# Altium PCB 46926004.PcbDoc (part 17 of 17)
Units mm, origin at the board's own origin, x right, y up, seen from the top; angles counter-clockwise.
Board outline 250 x 200 mm, 6 copper layers (Top Layer, INT1_GND, INT2_SIG, INT3_SIG, INT4_GND, Bottom Layer), stack 1.71 mm thick; 1450 components, 1293 nets, 5656 pads, 2307 vias.
Unrouted connection lines stored in the file: 2.
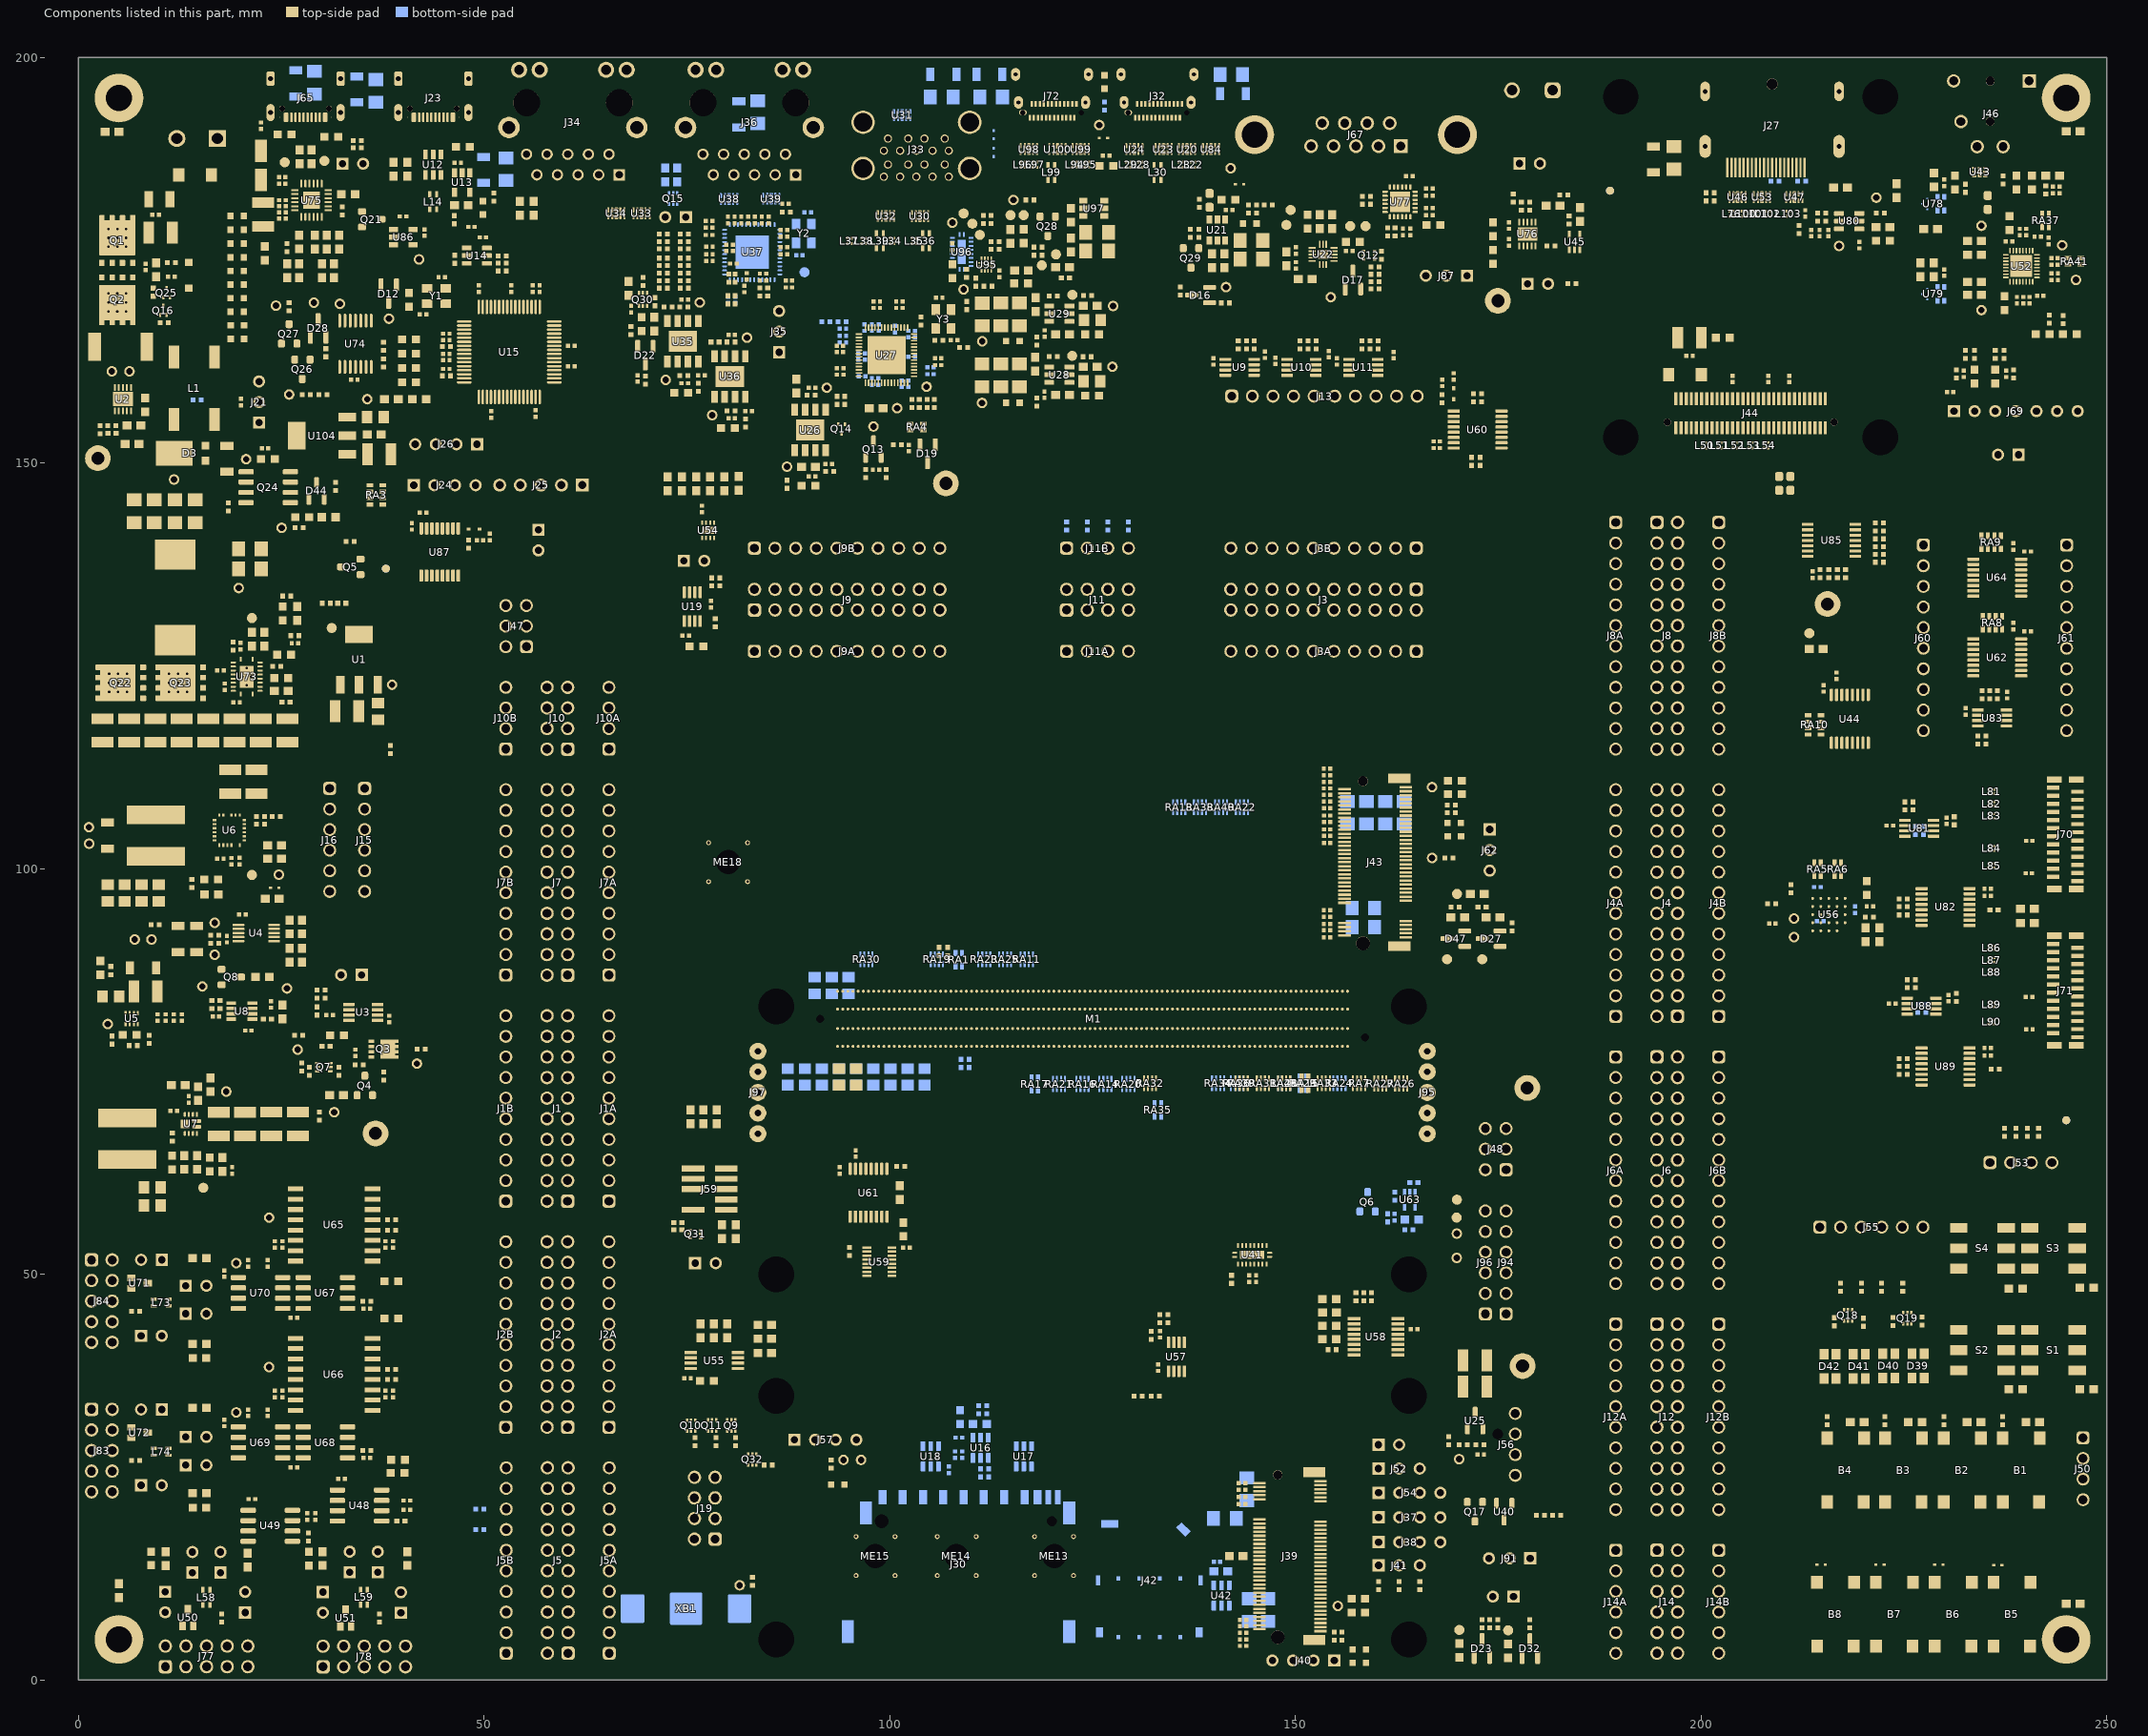
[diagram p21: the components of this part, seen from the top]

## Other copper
Top Layer:
  region net GND: 15.541,120.205 14.99,120.778 14.99,123.724 15.159,123.892 15.571,123.892 16.359,124.68 17.31,124.68 17.31,124.18 17.542,123.948 17.542,121.509 18.253,120.799 cw(c18.116,120.502) 18.253,120.205
  region net GND: 2.49,96.625 2.49,94.836 3.201,94.125 10.299,94.125 10.65,94.476 10.65,96.625
  region net NetC38_2: 2.49,97.375 10.65,97.375 11.65,98.375 13.691,98.375 14.129,98.813 14.129,101.982 13.435,102.675 4.682,102.675 4.382,102.975 2.782,102.975 2.49,102.683
  region net 5V_T: 11.5,92.425 11.5,95.575 12.033,96.108 14.992,96.108 15.35,95.75 15.35,92.425
  region net 5V: 15.35,90.225 15.35,87.075 14.817,86.542 11.858,86.542 11.5,86.9 11.5,90.225
  region net BUCK_1V8: 9.075,88.575 10.512,88.575 10.512,87.311 13.005,84.818 13.005,81.853 9.55,81.853 9.55,83.025 9.075,83.5
  region net VIN: 19.998,106.454 20.71,107.166 20.71,107.325 21.49,108.105 22.82,108.105 23.275,108.56 23.275,108.725 17.35,108.725 17.35,108.625 18.562,107.412 18.562,106.896 19.005,106.454
  region net VIN: 28.45,115.809 28.45,109.504 35.677,109.504 35.677,111.948 32.3,115.325 32.3,119.425 26.792,119.425 26.417,119.8 7.845,119.8 6.72,120.925 2.126,120.925 1.642,120.441 1.642,117.2 27.059,117.2
  region net VIN: 13.605,146.68 14.673,147.748 14.673,155.757 13.653,156.777 10.55,156.777 9.515,155.743 9.515,154.588 8.907,153.979 8.907,148.233 10.46,146.68
  region net VIN: 5.089,146.024 6.725,147.66 11.794,147.66 11.794,151.148 6.071,151.148 0.6,145.677 0.6,118.242 1.642,117.2 5.089,117.2
  region net VIN: 17.35,109.925 26.561,109.925 29.711,113.075 30.977,113.075 30.977,109.504 30.082,109.504 27.744,107.166 18.809,107.166 17.35,108.625
  region net NetC29_1: 13.159,69.092 12.308,69.092 11.825,69.575 11.06,69.575 9.86,70.775 2.075,70.775 2.075,67.992 12.642,67.992 13.159,67.992
  region net NetD1_2: 10.727,183.823 10.727,181.5 10.919,181.308 13.723,181.308 14.192,181.777 14.192,184.933 14.192,191.633 12.775,193.05 9.6,193.05 8.135,191.585 8.135,186.415 9.969,184.581
  region net PGND: 10.125,176.946 11.146,175.925 13.976,175.925 14.6,175.301 14.598,174.043 14.055,173.5 12.13,173.5 11.86,173.23 11.86,172.71 12.1,172.47 14.225,172.47 14.556,172.139 14.532,161.132 12.265,158.865 9.168,158.865 8.865,158.562 7.727,158.562 7.617,158.452 5.477,158.452 5.477,157.375 15.03,157.375 16.755,159.1 22.356,159.1 23.01,159.754 23.01,160.376 22.386,161 19.358,161 17.7,162.658 17.7,180.975 19.525,182.8 19.525,191.625 18.4,192.75 15.175,192.75 14.6,192.175 14.6,185.175 14.6,181.335 14.165,180.9 10.3,180.9 10.125,180.725
  region net 5V_S: 142.55,173.328 142.37,173.508 142.37,176.536 141.97,176.936 140.97,176.936 140.97,177.936 141.97,177.936 142.37,178.336 143.97,178.336 143.97,174.291 144.506,173.755 144.506,173.507 144.327,173.328
  region net USB_3_VBUS: 128.645,184.302 126.546,186.401 126.546,189.122 125.88,189.788 125.711,189.788 125.346,189.423 125.346,186.092 127.271,184.168 127.271,181.004 127.064,180.798 125.958,180.798 125.958,180.098 127.67,180.098 128.645,181.073 128.645,182.663
  region net USB1_VBUS: 141.67,179.536 141.67,181.478 141.37,181.778 141.37,183.529 142.71,183.529 142.71,186.909 142.383,187.236 141.657,187.236 141.27,186.849 141.27,184.979 141.795,184.454 141.795,184.246 140.879,184.246 140.37,183.63 140.37,181.269 140.97,180.669 140.97,179.536
  region net M2B_3V3: 143.695,7.685 144.215,7.685 144.475,7.425 146.325,7.425 146.325,4.515 145.566,3.755 143.695,3.755
  region net M2M_3V3: 154.04,102.89 154.56,102.89 155.037,103.367 155.037,105.65 156.825,105.65 156.825,107.45 155.033,107.45 155.033,109.15 156.825,109.15 156.825,111.678 156.714,111.789 155.352,111.789 154.553,112.589 154.033,112.589
  region net GND: 171.325,40.848 171.325,34.8 169.425,34.8 169.075,35.15 169.075,40.6 169.323,40.848
  region net 12V: 172.925,34.8 172.925,40.75 174.3,40.75 175.025,40.025 175.025,35.075 174.75,34.8
  region net M2B_3V3: 156.2,10.375 155.412,10.375 154.48,9.443 154.48,8.525 155.08,7.925 156.2,7.925
  region net M2M_3V3: 168.098,106.6 167.125,106.6 165.725,108 165.725,110.343 166.511,111.129 168.098,111.129
  region net M2M_3V3: 154.037,103.367 155.037,103.367 155.037,95.318 155.425,94.929 155.425,93.985 154.984,93.544 154.984,93.049 155.083,92.95 156.95,92.95 157.225,92.675 157.225,91.657 156.642,91.074 154.253,91.074 154.037,91.29
  region net M2B_3V3: 143.558,24.851 144.47,25.763 144.47,28.773 139.945,33.298 139.945,46.867 140.52,46.867 140.52,33.888 146.325,28.083 146.325,23.625 144.638,23.625 144.47,23.457 144.47,19.775 143.558,19.775
  region net GND: 140.02,180.536 140.02,179.308 139.919,179.206 139.07,179.206 139.07,178.289 141.67,178.289 141.67,179.206 140.809,179.206 140.72,179.295 140.72,180.536
  region net USB_3_VBUS: 125.98,190.55 126.685,191.254 126.685,192.026 126.235,192.475 125.438,192.475 125.011,192.048 125.011,191.31 125.771,190.55
  region net GND: 126.958,181.748 125.73,181.748 125.628,181.849 125.628,182.698 124.711,182.698 124.711,180.098 125.628,180.098 125.628,180.959 125.718,181.048 126.958,181.048
  region net 5V_S: 123.346,175.235 123.346,177.058 125.341,177.058 125.641,176.758 125.641,175.532 125.344,175.235
  region net 5V_S: 123.358,180.798 124.358,180.798 124.358,179.938 124.946,179.35 124.946,175.246 123.346,175.246
  region net GND: 126.146,177.538 126.146,179.362 128.141,179.362 128.441,179.062 128.441,177.836 128.144,177.538
  region net GND: 126.146,175.235 126.146,177.058 128.141,177.058 128.441,176.758 128.441,175.532 128.144,175.235
  region net USB5_5V: 119.644,167.173 119.352,167.173 119.352,166.103 113.82,166.103 112.001,164.285 111.106,164.285 110.46,164.931 110.46,167.753 119.644,167.753
  region net GND: 114.587,168.924 112.764,168.924 112.764,170.919 113.064,171.219 114.289,171.219 114.587,170.922
  region net GND: 112.299,168.914 110.476,168.914 110.476,170.909 110.776,171.209 112.002,171.209 112.299,170.912
  region net GND: 114.596,161.405 112.773,161.405 112.773,163.4 113.073,163.7 114.299,163.7 114.596,163.403
  region net GND: 112.272,161.405 110.449,161.405 110.449,163.4 110.749,163.7 111.975,163.7 112.272,163.403
  region net USB4_5V: 119.644,159.65 119.352,159.65 119.352,158.58 113.819,158.58 112.001,156.762 111.106,156.762 110.46,157.407 110.46,160.23 119.644,160.23
  pour cut-out: 151.496,172.165 150.896,172.165 150.896,173.165 151.496,173.165
  region net 5V_S: 125.3,165.163 127.158,165.163 127.246,165.251 127.246,166.476 127.158,166.563 125.3,166.563
  region net GND: 125.306,159.295 127.077,159.295 127.252,159.47 127.252,160.695 127.077,160.87 125.306,160.87
  region net NetC140_2: 124.575,165.388 124.575,167.753 122.154,167.753 122.154,167.168 122.687,167.168 123.054,166.801 123.054,165.388
  region net GND: 116.912,168.924 115.088,168.924 115.088,170.919 115.388,171.219 116.614,171.219 116.912,170.922
  region net GND: 125.325,166.826 127.096,166.826 127.271,167.001 127.271,168.226 127.096,168.401 125.325,168.401
  region net GND: 76.72,171.337 76.37,170.987 75.87,170.987 75.717,171.14 75.717,178.768 75.87,178.92 75.87,180.2 76.49,180.2 76.72,179.97
  region net 5V_S: 125.281,157.596 127.124,157.596 127.227,157.699 127.227,158.924 127.139,159.012 125.281,159.012
  region net NetC139_2: 124.545,157.837 124.545,160.23 122.199,160.23 122.199,159.65 122.732,159.65 123.099,159.283 123.099,157.837
  region net GND: 142.07,180.673 143.275,180.673 143.485,180.883 143.485,183.095 143.309,183.272 142.07,183.272
  region net GND: 145.173,174.239 147.72,174.239 147.72,178.336 145.173,178.336
  region net 3V3: 2.782,105.207 2.782,109.12 3.037,109.375 4.562,109.375 4.791,109.147 4.791,105.207
  region net 5V: 19.485,133.865 21.745,133.865 22.085,134.205 22.085,134.895 21.165,135.815 21.165,141.185 18.813,143.537 5.822,143.537 5.545,143.26 5.545,141.13 6.014,140.662 9.371,140.662 11.339,138.713 12.593,138.713 14.517,140.662 18.49,140.662 18.94,140.212 18.94,134.41
  region net VIN: 20.117,119.652 20.117,121.762 20.322,121.762 20.805,121.28 20.805,119.652
  region net NetC5_2: 5.767,174.677 5.767,174.288 6.261,173.794 8.555,173.794 8.555,173.37 7.856,172.671 3.822,172.671 3.825,172.673 3.825,173.35 3.551,173.624 3.329,173.624 3.159,173.794 2.552,174.401 2.552,174.677
  region net GND: 211.25,161.69 210.805,162.135 208.34,162.135 207.9,161.695 207.9,160.725 208.05,160.575 211.1,160.575 211.25,160.725
  region net 1V8: 210.027,159.602 210.6,160.175 212.59,160.175 212.967,159.798 212.967,156.555 212.842,156.43 210.12,156.43 210.027,156.523 210.027,157.15
  region net 3V3: 206.217,156.529 206.291,156.456 209.072,156.456 209.157,156.541 209.157,159.793 208.775,160.175 206.575,160.175 206.217,159.817
  region net 5V_S: 202.407,157.15 202.407,160.092 202.49,160.175 205.255,160.175 205.347,160.083 205.347,157.15
  region net VIN_DSI: 198.597,157.15 198.597,161.775 199.372,162.55 199.372,164.1 199.372,166.8 201.447,166.8 202.322,165.925 202.322,163.305 201.537,162.52 201.537,158.75 201.537,157.15
  region net VIN: 203.022,166.397 203.43,166.805 204.465,166.805 204.915,166.355 204.915,164.515 204.49,164.09 203.41,164.09 203.022,164.478 203.022,164.975
  region net GND: 197.772,159 197.772,166.8 196.472,166.8 193.3,163.628 193.3,162.087 196.387,159
  region net GND: 238.675,169.875 240.725,169.875 240.875,169.725 240.875,168.68 240.655,168.46 238.675,168.46 238.665,168.45 238.525,168.59 238.525,169.725
  region net NetC217_2: 237.4,170.05 237.875,170.05 238.1,170.275 240.725,170.275 240.725,171.695 240.56,171.86 240.135,171.86 240.135,171.36 239.825,171.05 238.5,171.05 237.4,171.05
  region net GND_ISO1: 25.798,56.427 25.423,56.052 23.266,56.052 22.519,56.799 22.519,58.136 25.22,60.837 25.798,60.837
  region net GND_ISO2: 25.798,38.01 25.423,37.635 23.266,37.635 22.519,38.382 22.519,39.719 25.22,42.42 25.798,42.42
  region net GND: 37.198,42.42 37.268,42.49 38.1,42.49 38.615,41.975 38.615,39.51 38.2,39.095 37.383,39.095 37.198,39.28
  region net GND: 37.203,60.835 37.273,60.905 38.105,60.905 38.62,60.39 38.62,57.925 38.205,57.51 37.387,57.51 37.203,57.695
  region net GND: 37.203,53.215 37.468,53.48 39.041,53.48 39.31,53.211 39.31,52.2 39.065,51.955 37.862,51.955 37.203,52.615
  region net GND_ISO1: 26.748,51.947 25.798,51.947 25.798,52.617 26.748,52.617 26.748,53.214 25.798,53.214 25.533,53.482 23.304,53.482 23.046,53.225 23.046,52.214 23.687,52.214 24.553,51.347 26.748,51.347
  region net GND_ISO2: 26.747,33.523 25.797,33.523 25.797,34.193 26.747,34.193 26.747,34.789 25.797,34.789 25.532,35.058 23.303,35.058 23.045,34.8 23.045,33.789 23.686,33.789 24.552,32.922 26.747,32.923
  region net 5V_ISO2: 26.748,35.47 25.797,35.47 23.305,35.47 22.995,35.78 22.995,36.565 23.47,37.04 25.445,37.04 25.445,36.355 25.731,36.07 26.748,36.07
  region net 5V_ISO1: 26.753,53.885 25.802,53.885 23.31,53.885 23,54.195 23,54.98 23.475,55.455 25.45,55.454 25.45,54.77 25.735,54.485 26.753,54.485
  region net GND: 37.198,34.8 37.463,35.065 39.036,35.065 39.305,34.797 39.305,33.785 39.06,33.54 37.858,33.54 37.198,34.2
  region net GND: 16.985,147.015 16.695,147.305 15.019,147.305 13.969,146.255 10.262,146.255 9.497,147.02 6.727,147.02 5.962,146.255 5.962,144.413 6.295,144.08 16.8,144.08 16.985,144.265
  region net NetC276_1: 7.6,120.677 7.6,123.892 9.437,123.892 9.437,124.825 10.892,124.825 10.892,120.677
  region net NetC300_1: 20.987,148.612 21.622,149.247 21.622,150.978 21.475,151.125 20.669,151.125 20.064,150.665 20.064,150.389 19.1,149.425 17.5,149.425 17.5,148.425 18.582,147.342 20.669,147.342 20.669,148.612
  region net NetD44_3: 26.018,145.437 25.178,145.437 24.775,145.84 24.775,146.94 25.178,147.342 32,147.342 32,147.977 23.952,147.977 23.45,147.475 23.45,145.325 23.972,144.802 26.018,144.802
  region net V_BUS_PD: 19.45,144.33 21.598,142.182 21.915,141.865 23.915,141.865 24.655,141.125 25.59,141.125 25.92,141.455 25.92,143.805 24.524,143.805 21.622,146.707 19.445,146.707
  region net 5V: 34.875,77.175 35.71,77.175 35.775,77.24 36.54,77.24 36.75,77.45 36.75,78.95 36.45,79.25 34.425,79.25 34.125,78.95 34.125,78.5 34.375,78.25 34.525,78.25 34.625,78.15 34.625,77.425
  region net 5V_S: 38.125,78.96 38.765,79.6 40.675,79.6 41.15,79.125 41.15,77.2 42.14,77.2 42.9,76.44 42.9,75.475 42.325,74.9 41.15,74.9 40.075,75.975 38.875,75.975 38.125,76.59
  region net GND: 105.039,73.975 105.039,72.114 104.8,71.875 87.187,71.875 86.2,72.862 86.2,73.6 86.575,73.975
  region net GND: 13.005,81.453 9.1,81.453 9.1,80.25 13.005,80.25
  region net NetL5_1: 6.175,84.85 6.175,83.5 6.702,82.973 6.702,82.665 6.955,82.665 6.955,82.98 7.475,83.5 7.475,84.85
  region net 3V3: 5.672,85.853 5.325,86.2 4,86.2 3.9,86.1 3.9,83.975 4.625,83.25 5.422,83.25 6.2,82.472 6.447,82.472 6.447,82.828 5.672,83.603
  region net GND: 3.625,85 3.05,85.575 1.925,85.575 1.425,85.075 1.425,82.75 2.416,81.759 4.081,81.759 4.673,81.167 5.55,81.167 5.55,82.325 5.05,82.825 4.3,82.825 3.625,83.5
  region net GND: 21.523,135.9 21.778,135.645 24.033,135.645 24.423,136.035 24.423,140.557 24.04,140.94 21.823,140.94 21.523,140.64
  region net 1V8: 5.127,86.975 4.805,87.297 4.805,89.641 5.071,89.907 6.615,89.907 6.875,89.647 6.875,86.975
  region net 12V: 14.559,69.117 15.076,69.117 15.93,69.971 15.93,70.625 16.73,71.425 27.589,71.425 28.632,70.381 28.632,68.898 28.266,68.531 16.786,68.531 16.78,68.525 16.605,68.7 14.559,68.7
  region net GND: 9.502,61.475 10.176,62.149 13.56,62.149 13.85,61.859 13.85,60.7 14.75,59.8 15.75,59.8 16.2,60.25 16.2,61.7 16.367,61.867 19.184,61.859 19.7,62.375 19.7,65.237 25.087,65.237 17.325,57.475 9.504,57.475
  region net 5V: 8.753,57.725 8.753,61.478 10.025,62.75 10.025,65.675 2.075,65.675 2.05,65.7 2.05,62.125 6.45,57.725
  region net NetC289_2: 22.899,190.551 24.03,189.42 24.03,187.875 23.235,187.08 21.77,187.08 20.993,187.857 20.993,189.496 22.048,190.551
  region net V_BUS_PD: 23.235,186.27 24.275,185.23 24.275,181.605 24.11,181.44 21.41,181.44 20.725,182.125 20.725,185.628 21.367,186.27 21.765,186.27
  region net GND: 116.896,161.405 115.073,161.405 115.073,163.4 115.373,163.7 116.599,163.7 116.896,163.403
  region net GND: 14.559,68.417 15.8,68.425 16.258,67.967 28.382,67.967 28.382,65.832 27.675,65.125 16.555,65.125 15.342,66.337 15.342,67.967 14.559,67.967
  region net GND: 1.175,111.595 1.175,115.758 1.942,116.525 26.792,116.525 27.7,115.617 27.7,113.317 25.108,110.725 15.508,110.725 14.638,111.595
  region net VPD: 15.65,149.05 15.25,149.45 15.25,152.901 15.574,153.225 15.578,153.22 16.43,153.22 16.675,152.975 16.899,152.975 17.127,153.204 19.6,153.204 19.6,150.55 19.235,150.185 16.99,150.185 16.99,149.05
  region net V+: 9.223,176.973 7.935,175.685 1.49,175.685 0.8,176.375 0.8,183.25 1.723,184.173 8.55,184.173 9.223,183.5
  region net GND: 17.023,106.302 16.725,106.6 16,106.6 15.641,106.241 15.641,104.95 16.229,104.361 17.023,104.361
  region net NetC34_1: 5.941,108.225 5.941,106.25 5.941,105.475 14.291,105.475 14.291,102.571 15.737,101.125 16.55,101.125 16.55,102.675 17.486,102.675 17.496,103.142 17.023,103.138 17.023,104.091 16.125,104.091 15.341,104.875 15.341,106.475 15.852,106.986 17.242,106.986 17.242,106.425 17.991,106.425 17.991,107.359 16.35,109 6.716,109
  pour cut-out: 4.791,105.475 14.291,105.475 14.291,102.675 4.791,102.675
  region net V+: 2.033,179.985 0.8,179.985 0.8,178.35 0.8,176.375 1.49,175.685 7.037,175.685 7.037,179.985
  pour cut-out: 8.023,151.864 5.223,151.864 5.223,152.864 8.023,152.864
  pour cut-out: 8.727,156.862 8.727,157.462 7.727,157.462 7.727,156.862
  pour cut-out: 96.193,165.995 96.906,166.708 102.181,166.708 102.995,165.893 102.995,160.693 102.194,159.892 97.008,159.892 97.001,159.885 96.193,160.693
  pour cut-out: 6.36,172.783 5.765,172.783 5.759,172.788 5.759,173.35 6.365,173.35
  pour cut-out: 3.82,172.783 3.225,172.783 3.219,172.788 3.219,173.35 3.825,173.35
  region net NetL1_2: 7.998,163.897 7.998,160.022 8.498,159.522 11.673,159.522 12.43,160.279 12.43,164.38 11.563,165.247 8.448,165.247 7.989,164.787
  region net NetQ2_5: 2.773,160.397 0.678,160.397 0.475,160.6 0.475,170.15 2.194,171.869 5.595,171.869 5.595,167.65 3.093,167.65 2.773,167.33
  region net NetC276_1: 14.445,128.167 14.445,125.25 13.315,124.12 10.142,124.12 9.445,124.817 9.445,128.167
  text "Aquila Development Board" at 214.528,67.147 h1.7
  text "Rev. 1.3" at 214.528,65.503 h1.7
  text ".DocumentNumber" at 214.528,64.003 h1.7
INT3_SIG:
  pour cut-out: 10.005,90.275 10.005,92.27 5.941,92.27 5.941,90.275
  region net 5V: 14.875,89.025 14.875,86.609 14.241,85.975 12.284,85.975 10.972,87.287 10.972,88.148 12.054,89.23 14.67,89.23
  region net 5V_T: 11.5,94.1 11.5,95.566 12.043,96.108 14.992,96.108 15.35,95.75 15.35,93.974 14.796,93.42 12.18,93.42
INT2_SIG:
  pour cut-out: 45.453,33.079 42.626,30.251 40.674,30.251 36.448,26.025 36.448,25.053 32.068,20.673 42.211,20.673 42.79,21.251 42.79,24.54 42.876,24.54 45.571,27.235 45.571,33.03
  pour cut-out: 141.118,140.879 141.118,151.719 141.339,151.94 141.773,151.94 141.993,151.719 141.993,141.575 141.298,140.879
  pour cut-out: 50.89,113.386 50.89,123.855 49.745,123.855 49.727,123.873 55.034,129.18 61.085,129.18 61.085,129.346 54.678,135.753 43.987,135.753 40.615,139.125 31.008,139.125 31.008,135.738 33.93,132.817 33.93,130.166 50.768,113.328
  pour cut-out: 39.456,124.012 39.456,86.567 32.156,79.81 41.323,79.81 44.034,82.52 48.691,87.177 50.768,89.254 50.768,112.701
  region net 5V: 15.35,90.225 15.35,87.075 14.817,86.542 11.858,86.542 11.5,86.9 11.5,90.225
  region net 5V_T: 11.5,92.425 11.5,95.575 12.033,96.108 14.992,96.108 15.35,95.75 15.35,92.425
  pour cut-out: 0,102.08 2.327,102.08 2.327,106.115 0,106.115
  pour cut-out: 190.8,149.231 190.8,122.36 181.574,122.36 181.574,149.231
  pour cut-out: 200.84,143.598 200.84,119.82 197.09,119.82 197.059,119.85 197.09,119.881 197.09,143.598
  pour cut-out: 172.5,114.6 174.066,114.6 174.066,106.2 172.5,106.2
  pour cut-out: 54.033,80.155 54.033,79.87 54.01,66.64 50.3,66.64 50.3,78.123 52.285,80.155 52.972,80.155
  pour cut-out: 131.45,194.3 136.4,194.3 136.6,194.1 136.6,193.937 134.965,192.302 131.45,192.302
  region net GND: 98.843,161.315 97.728,162.431 97.728,164.162 98.756,165.19 100.457,165.19 101.408,164.239 101.408,162.325 100.398,161.315
Bottom Layer:
  pour cut-out: 2.373,115 2.373,117.525 2.992,117.525 2.992,115
  region net V_BUS_PD: 25.92,141.455 25.59,141.125 24.269,141.125 23.217,142.176 23.217,143.982 24.355,145.12 25.574,145.12 25.92,144.774
  region net GND: 171.325,40.848 171.325,34.8 169.425,34.8 169.075,35.15 169.075,40.6 169.323,40.848
  region net 12V: 172.925,34.8 172.925,40.75 174.3,40.75 175.025,40.025 175.025,35.075 174.75,34.8
  region net M2B_3V3: 141.908,20.805 142.594,20.805 143.114,21.325 143.114,22.925 144.914,22.925 145.573,22.265 145.573,19.86 144.719,19.005 141.908,19.005
  region net M2B_3V3: 156.2,10.375 155.412,10.375 154.48,9.443 154.48,8.525 155.08,7.925 156.2,7.925
  region net M2B_3V3: 147.53,6.422 147.247,6.422 146.33,5.505 146.33,4.518 145.511,3.7 144.4,3.7 143.414,4.686 143.414,8.022 147.53,8.022
  region net GND: 158.975,96.056 160.744,96.056 161.409,95.391 161.409,92.25 161.059,91.9 158.975,91.9
  region net M2M_3V3: 157.775,91.9 157.075,91.2 154.815,91.2 154.515,91.5 154.515,94.992 155.58,96.056 157.775,96.056
  region net GND: 227.732,181.286 227.877,181.286 227.877,181.135 227.468,180.726 226.548,180.726 226.302,180.972 226.302,182.908 226.625,183.232 227.41,183.232 227.883,182.76 227.883,182.614 227.732,182.614 227.316,182.198 227.316,181.701
  region net GND: 227.732,170.17 227.877,170.17 227.877,170.018 227.468,169.609 226.548,169.609 226.302,169.856 226.302,171.792 226.625,172.115 227.41,172.115 227.882,171.643 227.882,171.497 227.732,171.497 227.316,171.081 227.316,170.585
  region net USB4_5V: 113.564,188.382 114.437,187.509 115.253,187.509 115.425,187.681 115.425,189.21 115.322,189.313 113.9,189.313 113.564,188.977
  region net USB5_5V: 113.493,190.167 114.236,190.909 114.818,190.909 114.99,190.737 114.99,189.826 114.811,189.646 113.634,189.646 113.493,189.787
  region net USB4_5V: 107.5,186.3 109.196,187.996 111.748,187.996 112.385,188.634 112.385,189 111.98,189 111.866,188.885 109.085,188.885 107.5,187.3 106.573,187.3 106.28,187.007 106.28,186.593 106.573,186.3
  region net USB5_5V: 106.78,189.5 112.201,189.5 112.478,189.778 112.478,190.077 112.224,190.331 107.877,190.331 107.708,190.5 106.595,190.5 106.426,190.331 106.426,189.854
  region net 5V: 14.875,89.025 14.875,86.609 14.241,85.975 12.284,85.975 10.972,87.287 10.972,88.148 12.054,89.23 14.67,89.23
  pour cut-out: 228.707,183.575 230.382,183.575 230.382,180.641 228.707,180.641
  region net GND: 95.675,87.375 95.225,87.825 90.46,87.825 90,87.365 90,85.975 95.675,85.975
  region net GND: 105.039,73.975 105.039,72.114 104.025,71.1 87.275,71.1 86.2,72.175 86.2,73.6 86.575,73.975
  region net 5V: 21.81,134.105 21.52,133.815 12.86,133.815 5.545,141.13 5.545,143.26 5.822,143.537 18.813,143.537 21.81,140.54
  region net VIN: 2.628,125.162 6.967,125.162 6.967,120.677 7.845,119.8 26.417,119.8 27.092,119.125 27.092,117.525 2.628,117.525
  region net GND: 26.792,116.525 27.25,116.067 27.25,111.225 26.35,110.325 26.325,110.35 4.6,110.35 2.628,112.322 2.628,115.228 3.925,116.525 4.325,116.525
  pour cut-out: 79.65,179.4 86.45,179.4 86.45,172.6 79.65,172.6
  pour cut-out: 30.45,198 30.45,195.8 25.475,195.8 25.475,198
  pour cut-out: 85.05,194.065 85.05,192.137 80.2,192.137 80.2,194.065
  pour cut-out: 48.875,185.02 48.875,187.22 53.85,187.22 53.85,185.02
  pour cut-out: 228.7,172.15 230.375,172.15 230.375,169.525 228.7,169.525
INT1_GND (plane layer: these items are gaps in the copper):
  rectangle: 3.39,176.353 6.19,179.153
  rectangle: 3.39,168.391 6.19,171.191
  rectangle: 3.494,121.52 6.294,124.32
  region: 0,18.55 16.125,18.55 21.25,23.675 28.55,23.675 31.55,26.675 31.55,43.45 24.525,43.45 19.349,38.274 0,38.274 0,34.975 17.445,34.975 25.139,42.669 27.698,42.669 28.522,41.845 28.522,26.772 27.475,25.725 21.5,25.725 16.15,20.375 0,20.375
  region: 0,38.274 19.349,38.274 24.525,43.45 31.55,43.45 31.55,60.325 28.3,63.575 24.32,63.575 17.395,56.65 0,56.65 0,53.351 17.445,53.351 25.139,61.045 27.698,61.045 28.522,60.221 28.522,45.248 27.499,44.225 23.825,44.225 19.35,39.75 0,39.75
INT4_GND (plane layer: these items are gaps in the copper):
  rectangle: 3.494,121.52 6.294,124.32
  rectangle: 3.39,168.391 6.19,171.191
  rectangle: 3.4,176.353 6.2,179.153
  rectangle: 177.4,177.45 179.775,179.025
  rectangle: 14.25,61.525 14.975,62.275
  rectangle: 161.725,180.95 164.225,183.45
  rectangle: 76.885,154.9 79.285,156.1
  rectangle: 69.5,154.95 71.9,156.15
  rectangle: 150.2,172.125 152.6,173.325
  rectangle: 28.175,181.85 29.275,182.95
  rectangle: 238.921,173.725 240.021,174.825
  region: 0,18.55 16.125,18.55 21.25,23.675 28.55,23.675 31.55,26.675 31.55,43.45 24.525,43.45 19.349,38.274 0,38.274 0,34.975 17.445,34.975 25.139,42.669 27.698,42.669 28.522,41.845 28.522,26.772 27.475,25.725 21.5,25.725 16.15,20.375 0,20.375
  region: 0,38.274 19.349,38.274 24.525,43.45 31.55,43.45 31.55,60.325 28.3,63.575 24.32,63.575 17.395,56.65 0,56.65 0,53.351 17.445,53.351 25.139,61.045 27.698,61.045 28.522,60.221 28.522,45.248 27.499,44.225 23.825,44.225 19.35,39.75 0,39.75
  lines w0.25: 0,86.09 14.793,86.09 15.433,86.73 15.433,88.862 11.62,92.675 10.7,92.675 5.194,98.181 5.194,116.106 2.433,118.867 2.433,124.439 4.275,126.281 4.275,138.031 5.58,139.335 19.786,139.335 20.492,140.042 20.492,141.543 18.649,143.386 0.015,143.386 ; 67.1,172.975 69.417,170.658 77.846,170.658 80.088,172.9 83.849,172.9 86.27,175.321 86.27,177.945 87.145,178.82 87.145,179.605 86.775,179.975 79.206,179.975 73.656,174.425 67.95,174.425 67.1,173.575 67.1,172.975

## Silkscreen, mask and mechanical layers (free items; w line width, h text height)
Top Overlay:
  circle w0.15: c18.825,186.8 r1
  circle w0.15: c9.55,186.875 r1
  region: 230.125,129.72 229.025,130.22 229.025,129.22
  region: 243.425,119.56 242.325,119.06 242.325,120.06
  region: 230.125,127.18 229.025,127.68 229.025,126.68
  region: 242.325,134.86 243.425,134.36 243.425,135.36
  region: 242.325,132.32 243.425,131.82 243.425,132.82
  region: 231.225,117.08 230.125,116.58 230.125,117.58
  region: 229.025,117.08 230.125,116.58 230.125,117.58
  region: 243.425,129.78 242.325,130.28 242.325,129.28
  region: 241.225,117.02 242.325,116.52 242.325,117.52
  region: 229.025,137.34 230.125,136.84 230.125,137.84
  region: 230.125,124.64 229.025,125.14 229.025,124.14
  region: 231.225,119.62 230.125,119.12 230.125,120.12
  region: 243.425,127.24 242.325,127.74 242.325,126.74
  region: 229.025,139.88 230.125,139.38 230.125,140.38
  region: 243.425,124.7 242.325,125.2 242.325,124.2
  region: 230.125,122.1 229.025,122.6 229.025,121.6
  region: 243.425,122.16 242.325,122.66 242.325,121.66
  region: 243.425,117.02 242.325,116.52 242.325,117.52
  region: 242.325,137.4 243.425,136.9 243.425,137.9
  region: 229.025,134.8 230.125,134.3 230.125,135.3
  region: 242.325,139.94 243.425,139.44 243.425,140.44
  region: 229.025,119.62 230.125,119.12 230.125,120.12
  region: 229.025,132.325 230.125,131.825 230.125,132.825
  region: 241.225,119.56 242.325,119.06 242.325,120.06
  lines w0.15: 0.278,18.854 16.15,18.854 21.642,24.346 27.321,24.346 28.94,25.965 28.94,43.167 ; 0.278,37.635 18.347,37.635 23.879,43.167 28.94,43.167 ; 0.278,56.052 17.702,56.052 23.875,62.225 27.968,62.225 28.94,61.253 28.94,43.167 ; 26.404,95.568 26.404,111.523 26.43,111.549 29.627,111.549 29.627,115.921 36.627,115.921 36.627,111.549 ; 26.413,95.559 29.627,95.559 ; 29.627,113.841 36.627,113.841 ; 32.327,95.559 33.927,95.559 ; 32.327,113.841 32.327,111.549 33.927,111.549 33.927,113.841
  text "20V/5A" at 35.94,193.439 h2 r90
  text "USB PD" at 34.441,193.126 h2 r90
  text "B" at 176.164,190.734 h2
  text "A" at 181.057,190.734 h2
  text "USB-C DFP" at 115.306,190.142 h2
  text "USB-C DRP" at 128.614,190.142 h2
  text "DEBUG" at 40.588,189.959 h2
  text "RS-485" at 176.332,188.834 h2
  text "AUDIO" at 242.121,187.856 h2 r90
  text "-" at 18.518,186.209 h2.54
  text "+" at 8.981,186.074 h2.54
  text "RS-232" at 154.562,185.811 h2
  text "DISPLAY PORT" at 199.541,185.541 h2 r90
  text "VIN 9-24V" at 1.844,184.193 h2
  text "RS-485 TERM" at 174.634,184.113 h1.3
  text "USB 3.0" at 100.056,182.434 h2
  text "ETHERNET 2" at 76.844,182.366 h2
  text "ETHERNET 1" at 57.24,182.163 h2
  text "(R)" at 228.55,181.449 h2
  text "VIN" at 15.175,179.85 h1.2
  text "12V" at 15.175,178.15 h1.2
  text "5V" at 15.175,176.45 h1.2
  text "5V_S" at 14.575,174.75 h1.2
  text "3V3" at 15.175,173.075 h1.2
  text "1V8" at 15.175,171.4 h1.2
  text "ON" at 164.788,170.324 h1.3
  text "OFF" at 168.701,170.324 h1.3
  text "(L)" at 228.55,170.253 h2
  text "PWR FAULT" at 11.775,169.725 h1
  text "AUTOPWRDN" at 164.4,168.874 h1.3
  text "PD FAULT" at 11.775,168.05 h1
  text "PWR_EN" at 12.962,166.313 h1
  text "RESET" at 14.076,164.767 h1
  text "RETRY" at 23.658,161.475 h1.3 r90
  text "OFF" at 25.036,157.626 h1.3 r90
  text "3V3" at 162.88,154.626 h1.3 r90
  text "3V3" at 165.42,154.626 h1.3 r90
  text "GND" at 147.646,154.132 h1.3 r90
  text "GND" at 155.266,154.132 h1.3 r90
  text "ON" at 25.036,153.713 h1.3 r90
  text "I2C1_SCL_3V" at 144.999,149.187 h1.3 r90
  text "I2C2_SCL_3V" at 152.619,149.187 h1.3 r90
  text "I2C6_SCL_3V" at 160.239,149.187 h1.3 r90
  text "I2C1_SDA_3V" at 142.459,149.059 h1.3 r90
  text "I2C2_SDA_3V" at 150.079,149.059 h1.3 r90
  text "I2C6_SDA_3V" at 157.699,149.059 h1.3 r90
  text "DP_1_HPD" at 234.25,148.262 h1.3
  text "MIPI DSI" at 201.24,147.464 h2
  text "LEVEL SHIFT" at 230.965,145.284 h2
  text "1.8V" at 230.128,142.968 h2
  text "3.3V" at 238.791,142.968 h2
  text "AQUILA_B35" at 180.625,142.371 h1.3
  text "UART_1_RXD" at 203.83,142.377 h1.3
  text "GPIO_01" at 83.629,141.16 h1.3 r90
  text "GPIO_02" at 86.169,141.16 h1.3 r90
  text "GPIO_03" at 88.709,141.16 h1.3 r90
  text "GPIO_04" at 91.249,141.16 h1.3 r90
  text "GPIO_05" at 93.789,141.16 h1.3 r90
  text "GPIO_06" at 96.329,141.16 h1.3 r90
  text "GPIO_07" at 98.869,141.16 h1.3 r90
  text "GPIO_08" at 101.409,141.16 h1.3 r90
  text "PWR_1V8_MOCI" at 103.949,141.16 h1.3 r90
  text "GND" at 106.596,141.16 h1.3 r90
  text "I2C_2_SDA" at 122.109,141.16 h1.3 r90
  text "I2C_2_SCL" at 124.649,141.16 h1.3 r90
  text "I2C_6_SDA" at 127.191,141.16 h1.3 r90
  text "I2C_6_SCL" at 129.731,141.16 h1.3 r90
  text "USB_1_INT#" at 142.349,141.16 h1.3 r90
  text "USB_1_OC#" at 144.889,141.16 h1.3 r90
  text "USB_1_VBUS" at 147.429,141.16 h1.3 r90
  text "USB_1_EN" at 149.969,141.16 h1.3 r90
  text "USB_2_EN" at 152.509,141.16 h1.3 r90
  text "I2S_1_MCLK" at 155.049,141.16 h1.3 r90
  text "I2S_1_D_IN" at 157.589,141.16 h1.3 r90
  text "I2S_1_D_OUT" at 160.129,141.16 h1.3 r90
  text "I2S_1_SYNC" at 162.669,141.16 h1.3 r90
  text "I2S_1_BCLK" at 165.209,141.16 h1.3 r90
  text "AQUILA_B37" at 180.642,139.831 h1.3
  text "UART_1_TXD" at 203.83,139.837 h1.3
  text "USB" at 55.45,138.75 h1.3 r90
  text "AQUILA_B38" at 180.642,137.291 h1.3
  text "UART_1_RTS" at 203.83,137.291 h1.3
  text "FTDI GPIO PWR" at 53.95,135.6 h1.3 r90
  text "AQUILA_B36" at 180.631,134.751 h1.3
  text "UART_1_CTS" at 203.83,134.751 h1.3
  text "AQUILA_B31" at 180.78,132.211 h1.3
  text "UART_2_RXD" at 203.83,132.217 h1.3
  text "CTRL_RESET_MICO#" at 39.146,132.131 h1.3
  text "CTRL_FORCE_OFF_MOCI#" at 56.87,132.131 h1.3
  text "I/O" at 225.693,130.437 h1.3 r90
  text "I/O" at 247.55,130.438 h1.3 r90
  text "AQUILA_B33" at 180.64,129.671 h1.3
  text "UART_2_TXD" at 203.83,129.677 h1.3
  text "CTRL_PWR_BTN_MICO#" at 37.276,129.591 h1.3
  text "AQUILA_B34" at 180.616,127.131 h1.3
  text "UART_2_RTS" at 203.83,127.131 h1.3
  text "PWR_BTN#" at 56.87,127.052 h1.3
  text "GND" at 48.552,126.944 h1.3
  text "AQUILA_B32" at 180.649,124.591 h1.3
  text "UART_2_CTS" at 203.83,124.591 h1.3
  text "GND" at 106.596,122.682 h1.3 r90
  text "AQUILA_D19" at 180.644,122.051 h1.3
  text "UART_3_RXD" at 203.83,122.057 h1.3
  text "GND" at 48.552,121.944 h1.3
  text "GND" at 67.03,121.944 h1.3
  text "AQUILA_D20" at 180.648,119.511 h1.3
  text "UART_3_TXD" at 203.83,119.517 h1.3
  text "1V8" at 49.045,119.41 h1.3
  text "1V8" at 67.03,119.41 h1.3
  text "AQUILA_C21" at 93.789,118.11 h1.3 r90
  text "AQUILA_B21" at 162.669,118.11 h1.3 r90
  text "AQUILA_D23" at 83.629,117.97 h1.3 r90
  text "AQUILA_C20" at 91.249,117.978 h1.3 r90
  text "AQUILA_C22" at 96.329,117.979 h1.3 r90
  text "AQUILA_C23" at 98.869,117.97 h1.3 r90
  text "AQUILA_C17" at 124.649,117.972 h1.3 r90
  text "AQUILA_C18" at 127.191,117.972 h1.3 r90
  text "AQUILA_C19" at 129.731,117.974 h1.3 r90
  text "AQUILA_B77" at 149.969,117.972 h1.3 r90
  text "AQUILA_B80" at 152.509,117.978 h1.3 r90
  text "AQUILA_B23" at 157.589,117.97 h1.3 r90
  text "AQUILA_B22" at 160.129,117.979 h1.3 r90
  text "AQUILA_B20" at 165.209,117.978 h1.3 r90
  text "AQUILA_D24" at 86.169,117.946 h1.3 r90
  text "AQUILA_D25" at 88.709,117.955 h1.3 r90
  text "AQUILA_C24" at 101.409,117.946 h1.3 r90
  text "AQUILA_B96" at 103.949,117.961 h1.3 r90
  text "AQUILA_C16" at 122.109,117.961 h1.3 r90
  text "AQUILA_B74" at 142.349,117.946 h1.3 r90
  text "AQUILA_B75" at 144.889,117.955 h1.3 r90
  text "AQUILA_B76" at 147.429,117.961 h1.3 r90
  text "AQUILA_B24" at 155.049,117.946 h1.3 r90
  text "I2C" at 225.725,117.48 h1.3 r90
  text "I2C" at 247.583,117.481 h1.3 r90
  text "I2C_1_SCL" at 45.063,116.971 h1.3
  text "AQUILA_D08" at 67.03,116.971 h1.3
  text "AQUILA_D21" at 180.78,116.971 h1.3
  text "UART_4_RXD" at 203.83,116.977 h1.3
  text "M.2" at 158.42,114.946 h2.03
  text "I2C_1_SDA" at 44.905,114.431 h1.3
  text "AQUILA_D07" at 67.03,114.431 h1.3
  text "AQUILA_D22" at 180.649,114.431 h1.3
  text "UART_4_TXD" at 203.83,114.437 h1.3
  text "Power" at 30.568,114.27 h2
  text "Key M" at 157.281,112.941 h2.03
  text "VIN" at 26.728,109.48 h1.3
  text "AQUILA_B73" at 180.64,109.391 h1.3
  text "OSPI_1_IO7" at 203.83,109.391 h1.3
  text "GND" at 48.552,109.324 h1.3
  text "GND" at 67.03,109.324 h1.3
  text "5V_S" at 26.728,107.17 h1.3
  text "AQUILA_B72" at 180.649,106.851 h1.3
  text "OSPI_1_IO6" at 203.83,106.851 h1.3
  text "1V8" at 49.095,106.79 h1.3
  text "1V8" at 67.03,106.79 h1.3
  text "GND" at 26.728,104.416 h1.3
  text "CTRL_MCLK_MOCI" at 40.372,104.351 h1.3
  text "AQUILA_A14" at 67.03,104.351 h1.3
  text "AQUILA_B71" at 180.78,104.311 h1.3
  text "OSPI_1_IO5" at 203.83,104.311 h1.3
  text "3V3" at 26.728,101.876 h1.3
  text "CTRL_WAKE1_MICO#" at 38.824,101.811 h1.3
  text "AQUILA_D06" at 67.03,101.811 h1.3
  text "AQUILA_B70" at 180.648,101.771 h1.3
  text "OSPI_1_IO4" at 203.83,101.771 h1.3
  text "MIPI CSI 1" at 249.126,100.15 h2 r90
  text "3V3" at 26.728,99.336 h1.3
  text "CTRL_RESET_MOCI#" at 39.146,99.271 h1.3
  text "AQUILA_D05" at 67.03,99.271 h1.3
  text "AQUILA_B60" at 180.648,99.231 h1.3
  text "QSPI_1_IO3" at 203.83,99.231 h1.3
  text "1V8" at 26.728,96.796 h1.3
  text "CTRL_PWR_EN_MOCI" at 38.757,96.731 h1.3
  text "AQUILA_B95" at 67.03,96.731 h1.3
  text "AQUILA_B61" at 180.78,96.691 h1.3
  text "QSPI_1_IO2" at 203.83,96.691 h1.3
  text "CTRL_FORCE_OFF_MOCI#" at 35.984,94.191 h1.3
  text "AQUILA_B94" at 67.03,94.191 h1.3
  text "AQUILA_B67" at 180.642,94.187 h1.3
  text "QSPI_1_IO1" at 203.83,94.151 h1.3
  text "CTRL_PWR_BTN_MICO#" at 37.276,91.651 h1.3
  text "AQUILA_B93" at 67.03,91.651 h1.3
  text "AQUILA_B68" at 180.642,91.651 h1.3
  text "QSPI_1_IO0" at 203.83,91.651 h1.3
  text "CTRL_RESET_MICO#" at 39.146,89.111 h1.3
  text "AQUILA_B92" at 67.03,89.111 h1.3
  text "AQUILA_B65" at 180.625,89.111 h1.3
  text "QSPI_1_SCK" at 203.83,89.111 h1.3
  text "CTRL_RECOVERY_MICO#" at 36.501,86.571 h1.3
  text "AQUILA_B91" at 67.03,86.571 h1.3
  text "AQUILA_B66" at 180.631,86.571 h1.3
  text "QSPI_1_CS1#" at 203.83,86.571 h1.3
  text "AQUILA_B62" at 180.649,84.031 h1.3
  text "QSPI_1_CS2#" at 203.83,84.031 h1.3
  text "CAN_4_RX" at 45.009,81.571 h1.3
  text "AQUILA_B56" at 67.03,81.571 h1.3
  text "AQUILA_B63" at 180.64,81.491 h1.3
  text "QSPI_1_DQS" at 203.83,81.491 h1.3
  text "MIPI CSI 2" at 249.126,80.45 h2 r90
  text "CAN_4_TX" at 45.138,79.031 h1.3
  text "AQUILA_B55" at 67.03,79.031 h1.3
  text "CAN_3_RX" at 45.009,76.491 h1.3
  text "AQUILA_B54" at 67.03,76.491 h1.3
  text "AQUILA_B17" at 180.642,76.491 h1.3
  text "GPIO_09_CSI_1" at 203.83,76.491 h1.3
  text "CAN_3_TX" at 45.138,73.951 h1.3
  text "AQUILA_B53" at 67.03,73.951 h1.3
  text "AQUILA_B18" at 180.642,73.951 h1.3
  text "GPIO_10_CSI_1" at 203.83,73.951 h1.3
  text "CAN_2_RX" at 45.009,71.411 h1.3
  text "AQUILA_B51" at 67.03,71.411 h1.3
  text "AQUILA_A11" at 180.78,71.411 h1.3
  text "GPIO_11_CSI_1" at 203.83,71.411 h1.3
  text "ADC" at 172.754,70.567 h2
  text "CAN_2_TX" at 45.138,68.871 h1.3
  text "AQUILA_B50" at 67.03,68.871 h1.3
  text "AQUILA_B19" at 180.644,68.871 h1.3
  text "GPIO_12_CSI_1" at 203.83,68.871 h1.3
  text "GND" at 169.19,67.559 h1.3
  text "1V8" at 177.671,67.565 h1.3
  text "CAN_1_RX" at 45.009,66.331 h1.3
  text "AQUILA_B49" at 67.03,66.331 h1.3
  text "AQUILA_A12" at 180.649,66.331 h1.3
  text "I2C_4_CSI1_SDA" at 203.83,66.331 h1.3
  text "JTAG" at 74.775,66.049 h2.03
  text "ADC_1" at 168.065,65.126 h1.3
  text "ADC_3" at 177.656,65.126 h1.3
  text "CAN_1_TX" at 45.138,63.791 h1.3
  text "AQUILA_B48" at 67.03,63.791 h1.3
  text "AQUILA_A13" at 180.64,63.791 h1.3
  text "I2C_4_CSI1_SCL" at 203.83,63.791 h1.3
  text "ADC_2" at 167.938,62.586 h1.3
  text "ADC_4" at 177.656,62.591 h1.3
  text "PWM_2" at 47.031,61.257 h1.3
  text "AQUILA_C26" at 67.03,61.251 h1.3
  text "AQUILA_C04" at 180.616,61.251 h1.3
  text "GPIO_16_CSI_2" at 203.83,61.251 h1.3
  text "S4" at 236.118,58.951 h1.3 r90
  text "S3" at 238.658,58.951 h1.3 r90
  text "S2" at 241.198,58.951 h1.3 r90
  text "S1" at 243.738,58.951 h1.3 r90
  text "PWM_1" at 47.162,58.717 h1.3
  text "AQUILA_C25" at 67.03,58.711 h1.3
  text "AQUILA_C03" at 180.64,58.711 h1.3
  text "GPIO_15_CSI_2" at 203.83,58.711 h1.3
  text "AQUILA_C02" at 180.649,56.171 h1.3
  text "GPIO_14_CSI_2" at 203.83,56.171 h1.3
  text "CTRL_TAMPER0" at 41.838,53.711 h1.3
  text "AQUILA_C14" at 67.03,53.711 h1.3
  text "AQUILA_C01" at 180.78,53.631 h1.3
  text "GPIO_13_CSI_2" at 203.83,53.631 h1.3
  text "CAN1 GND" at 5.727,52.988 h1.3
  text "CTRL_TAMPER1" at 41.97,51.171 h1.3
  text "AQUILA_C15" at 67.03,51.171 h1.3
  text "AQUILA_C05" at 180.625,51.091 h1.3
  text "I2C_5_CSI2_SDA" at 203.83,51.091 h1.3
  text "GND" at 215.168,51.001 h1.3 r90
  text "D42" at 217.708,51.001 h1.3 r90
  text "D41" at 220.248,51.001 h1.3 r90
  text "D40" at 222.788,51.001 h1.3 r90
  text "D39" at 225.328,51.001 h1.3 r90
  text "1.8V" at 227.868,51.001 h1.3 r90
  text "JTAG SEL" at 74.4,48.9 h1.2
  text "SPI_2_MOSI" at 44.355,48.631 h1.3
  text "AQUILA_D17" at 67.03,48.631 h1.3
  text "AQUILA_C06" at 180.631,48.551 h1.3
  text "I2C_5_CSI2_SCL" at 203.83,48.551 h1.3
  text "1-2: FTDI JTAG" at 74.4,47.7 h1.2
  text "SPI_2_MISO" at 44.326,46.091 h1.3
  text "AQUILA_D15" at 67.03,46.091 h1.3
  text "SPI_2_CS" at 45.693,43.551 h1.3
  text "AQUILA_D16" at 67.03,43.551 h1.3
  text "AQUILA_B26" at 180.631,43.551 h1.3
  text "I2S_2_BCLK_DSI" at 203.83,43.551 h1.3
  text "CAN1 TERM" at 18.637,41.46 h1.3 r90
  text "SPI_2_CLK" at 44.864,41.011 h1.3
  text "AQUILA_D14" at 67.03,41.011 h1.3
  text "AQUILA_B27" at 180.642,41.011 h1.3
  text "I2S_2_SYNC_DSI" at 203.83,41.011 h1.3
  text "CAN1 PWR" at 5.727,39.888 h1.3
  text "SPI_1_MOSI" at 44.355,38.471 h1.3
  text "AQUILA_D11" at 67.03,38.471 h1.3
  text "AQUILA_B28" at 180.642,38.471 h1.3
  text "I2S_2_D_OUT_DSI" at 203.83,38.471 h1.3
  text "SPI_1_MISO" at 44.326,35.931 h1.3
  text "AQUILA_D10" at 67.03,35.931 h1.3
  text "AQUILA_B29" at 180.644,35.931 h1.3
  text "I2S_2_D_IN_DSI" at 203.83,35.931 h1.3
  text "FAN" at 175.7,34.825 h2.03
  text "CAN2 GND" at 5.727,34.605 h1.3
  text "SPI_1_CS" at 45.693,33.391 h1.3
  text "AQUILA_D09" at 67.03,33.391 h1.3
  text "AQUILA_B26" at 180.631,33.391 h1.3
  text "I2S_2_BCLK_M2B" at 203.83,33.391 h1.3
  text "SPI_1_CLK" at 44.864,30.851 h1.3
  text "AQUILA_D12" at 67.03,30.851 h1.3
  text "AQUILA_B27" at 180.642,30.851 h1.3
  text "I2S_2_SYNC_M2B" at 203.83,30.851 h1.3
  text "B1" at 243.049,29.15 h1.3
  text "M.2" at 147.92,28.646 h2.03
  text "AQUILA_B28" at 180.642,28.311 h1.3
  text "I2S_2_D_OUT_M2B" at 203.83,28.311 h1.3
  text "Key B" at 146.866,27.081 h2.03
  text "B2" at 243.049,26.61 h1.3
  text "AQUILA_B29" at 180.644,25.771 h1.3
  text "I2S_2_D_IN_M2B" at 203.83,25.771 h1.3
  text "GND" at 48.552,25.744 h1.3
  text "GND" at 67.03,25.744 h1.3
  text "FORCE_OFF_MOCI#" at 80.124,24.676 h1.3
  text "B3" at 243.049,24.07 h1.3
  text "1V8" at 49.095,23.21 h1.3
  text "1V8" at 67.03,23.21 h1.3
  text "1V8" at 185.895,23.13 h1.3
  text "1V8" at 203.83,23.13 h1.3
  text "CAN2 TERM" at 18.627,23.122 h1.3 r90
  text "RECOVERY_MICO#" at 80.124,22.136 h1.3
  text "B4" at 243.049,21.53 h1.3
  text "CAN2 PWR" at 5.795,21.288 h1.3
  text "I2C_3_DSI1_SCL" at 41.834,20.771 h1.3
  text "AQUILA_B41" at 67.03,20.771 h1.3
  text "GND" at 185.352,20.584 h1.3
  text "GND" at 203.83,20.584 h1.3
  text "PWR_BTN_MICO#" at 80.124,19.596 h1.3
  text "I2C_3_DSI1_SDA" at 41.675,18.231 h1.3
  text "AQUILA_B40" at 67.03,18.231 h1.3
  text "RESET_MICO#" at 80.124,17.056 h1.3
  text "CAN3 TERM" at 11.891,16.971 h1.3
  text "CAN4 TERM" at 31.308,16.955 h1.3
  text "3-Wire" at 172.599,16.25 h1.3
  text "4-Wire" at 176.512,16.25 h1.3
  text "PWM_4_DP" at 44.765,15.697 h1.3
  text "AQUILA_B58" at 67.03,15.691 h1.3
  text "AQUILA_C37" at 180.642,15.691 h1.3
  text "PCIE_1_CLKREQ" at 203.83,15.691 h1.3
  text "FTDI GPIO" at 74.849,13.724 h2
  text "FAN SEL" at 167.15,13.675 h1.3
  text "GPIO_17_DSI_1" at 42.545,13.151 h1.3
  text "AQUILA_B42" at 67.03,13.151 h1.3
  text "AQUILA_C38" at 180.642,13.151 h1.3
  text "PCIE_1_RESET#" at 203.83,13.151 h1.3
  text "1-2: 1kHz-40kHz PWM" at 167.383,11.484 h1.2
  text "GPIO_18_DSI_1" at 42.545,10.611 h1.3
  text "AQUILA_B43" at 67.03,10.611 h1.3
  text "AQUILA_C36" at 180.631,10.611 h1.3
  text "PCIE_WAKE#" at 203.83,10.611 h1.3
  text "GPIO_19_DSI_1" at 42.545,8.071 h1.3
  text "AQUILA_B44" at 67.03,8.071 h1.3
  text "AQUILA_C34" at 180.616,8.071 h1.3
  text "PCIE_2_CLKREQ" at 203.83,8.071 h1.3
  text "CAN3 PWR" at 23.287,6.266 h1.3 r90
  text "CAN4 PWR" at 42.469,6.25 h1.3 r90
  text "CAN3 GND" at 9.512,6.195 h1.3 r90
  text "CAN4 GND" at 28.944,6.174 h1.3 r90
  text "GPIO_20_DSI_1" at 42.545,5.531 h1.3
  text "AQUILA_B45" at 67.03,5.531 h1.3
  text "AQUILA_C35" at 180.625,5.531 h1.3
  text "PCIE_2_RESET#" at 203.83,5.531 h1.3
  text "PWM_3_DSI" at 44.465,2.991 h1.3
  text "AQUILA_B46" at 67.03,2.991 h1.3
  text "GND" at 185.352,2.884 h1.3
  text "GND" at 203.83,2.884 h1.3
  text "RECOVERY" at 213.069,1.465 h1.3
  text "RESET" at 221.412,1.465 h1.3
  text "PWR_KILL" at 228.027,1.465 h1.3
  text "ON/OFF" at 235.785,1.465 h1.3
Bottom Overlay:
  text "BUMPER" at 89.463,141.638 h1.5
  text "BUMPER" at 167.569,141.638 h1.5
  text "BUMPER" at 128.463,76.256 h1.5
  text "BUMPER" at 167.347,43.553 h1.5
  text "BUMPER" at 89.569,43.338 h1.5
  text "BUMPER" at 128.463,31.913 h1.5
  text "SD CARD" at 105.454,23.774 h2
  text "RTC BATTERY" at 81.15,14.158 h2
Top Solder:
  text "Aquila Development Board" at 214.528,67.147 h1.7
  text "Rev. 1.3" at 214.528,65.503 h1.7
  text ".DocumentNumber" at 214.528,64.003 h1.7
Mechanical 1:
  circle w0.254: c163.994,50 r4.5
  circle w0.254: c85.994,50 r4.5
  circle w0.254: c85.994,148.25 r4.5
  circle w0.254: c163.994,148.25 r4.5
  text "BUMPER" at 89.463,153.488 h1.5
  text "BUMPER" at 167.463,153.488 h1.5
  text "BUMPER" at 89.463,55.238 h1.5
  text "BUMPER" at 167.463,55.238 h1.5
M30-Single_50R _TOP:
  drawing of 884 lines, arcs and shapes, not listed
M31-Single_50R _INT2:
  lines w0.18: 156.413,65.574 156.413,65.62 157.116,65.62 160.017,68.521 160.017,76.109 157.475,78.651 157.475,83.831 156.991,84.315
M32-Single_50R _BOT:
  drawing of 644 lines, arcs and shapes, not listed
M33-DIFF_95R_TOP:
  drawing of 305 lines, arcs and shapes, not listed
M35-DIFF_95R_BOT:
  drawing of 315 lines, arcs and shapes, not listed
M36-DIFF_100R_TOP:
  drawing of 178 lines, arcs and shapes, not listed
M37-DIFF_90R_TOP:
  drawing of 2544 lines, arcs and shapes, not listed
M39-DIFF_90R_BOT:
  drawing of 846 lines, arcs and shapes, not listed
